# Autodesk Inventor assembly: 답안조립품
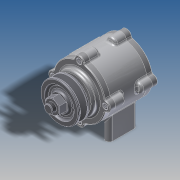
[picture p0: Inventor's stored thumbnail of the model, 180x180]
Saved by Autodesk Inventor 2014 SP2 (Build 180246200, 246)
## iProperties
Created: 2015-03
Part Number: 답안조립품
Document SubType Name: Assembly
Designer: 201-07
Author: 201-07
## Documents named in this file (11)
- C:\Users\201-07\Desktop\450305v1005\답안조립품.iam
- C:\Users\201-07\Desktop\450305v1005\본체.ipt
- C:\Users\201-07\Desktop\450305v1005\축.ipt
- C:\Users\201-07\Desktop\450305v1005\베어링 6204.ipt
- C:\Users\201-07\Desktop\450305v1005\커버2.ipt
- C:\Users\201-07\Desktop\450305v1005\M 4 x 12.ipt
- C:\Users\201-07\Desktop\450305v1005\커버.ipt
- C:\Users\201-07\Desktop\450305v1005\오일실.ipt
- C:\Users\201-07\Desktop\450305v1005\키(4 x 4 x 12).ipt
- C:\Users\201-07\Desktop\450305v1005\V벨트풀리.ipt
- C:\Users\201-07\Desktop\450305v1005\너트 M12x1.25.ipt
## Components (14 placed, 6 different names)
1. KS B 2023 6204 - 20 x 47 x 14:1
2. KS B 2023 6204 - 20 x 47 x 14:2
3. KS B 2804 D D - 20 32 8:1
4. KS B 1311 (I) 4 x 4 x 12:1 — 각도:1, 각도:2
5. 그루브 풀리1:1 — 각도:2, 각도:3
6. KS B 1012 클래스 1 일반 - 미터 M12x1.25:1
7. KS B 1003 - 미터 M 4 x 12:1
8. KS B 1003 - 미터 M 4 x 12:2
9. KS B 1003 - 미터 M 4 x 12:3
10. KS B 1003 - 미터 M 4 x 12:4
11. KS B 1003 - 미터 M 4 x 12:5
12. KS B 1003 - 미터 M 4 x 12:6
13. KS B 1003 - 미터 M 4 x 12:7
14. KS B 1003 - 미터 M 4 x 12:8
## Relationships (3: Angle 3)
- 각도:1 [Angle]: KS B 1311 (I) 4 x 4 x 12:1
- 각도:2 [Angle]: KS B 1311 (I) 4 x 4 x 12:1 ↔ 그루브 풀리1:1
- 각도:3 [Angle]: 그루브 풀리1:1
